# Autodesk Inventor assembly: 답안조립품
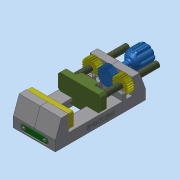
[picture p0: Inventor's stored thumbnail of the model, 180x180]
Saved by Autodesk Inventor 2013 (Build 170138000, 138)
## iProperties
Created: 2017-04
Part Number: 답안조립품
Document SubType Name: Assembly
Designer: dgall
Mass: 958.422 g
Surface Area: 784.418 cm^2
Volume: 280.832 cm^3
Density: 3.4128 g/cm^3
Author: dgall
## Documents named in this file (10)
- C:\Users\dgall\Desktop\370407V1008\답안조립품.iam
- C:\Users\dgall\Desktop\370407V1008\바이스본체 A.ipt
- C:\Users\dgall\Desktop\370407V1008\바이스본체 B.ipt
- C:\Users\dgall\Desktop\370407V1008\고정 플레이트.ipt
- C:\Users\dgall\Desktop\370407V1008\슬라이딩 부품.ipt
- C:\Users\dgall\Desktop\370407V1008\핸들.ipt
- C:\Users\dgall\Desktop\370407V1008\스퍼기어.ipt
- C:\Users\dgall\Desktop\370407V1008\지지대.ipt
- C:\Users\dgall\Desktop\370407V1008\십자오목머리나사 M4.ipt
- C:\Users\dgall\Desktop\370407V1008\십자오목머리나사 M3.ipt
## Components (3 placed, 2 different names)
1. 고정 플레이트:1
2. 고정 플레이트:2
3. 핸들:1 — 각도:1
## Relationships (1: Angle 1)
- 각도:1 [Angle]: 핸들:1
